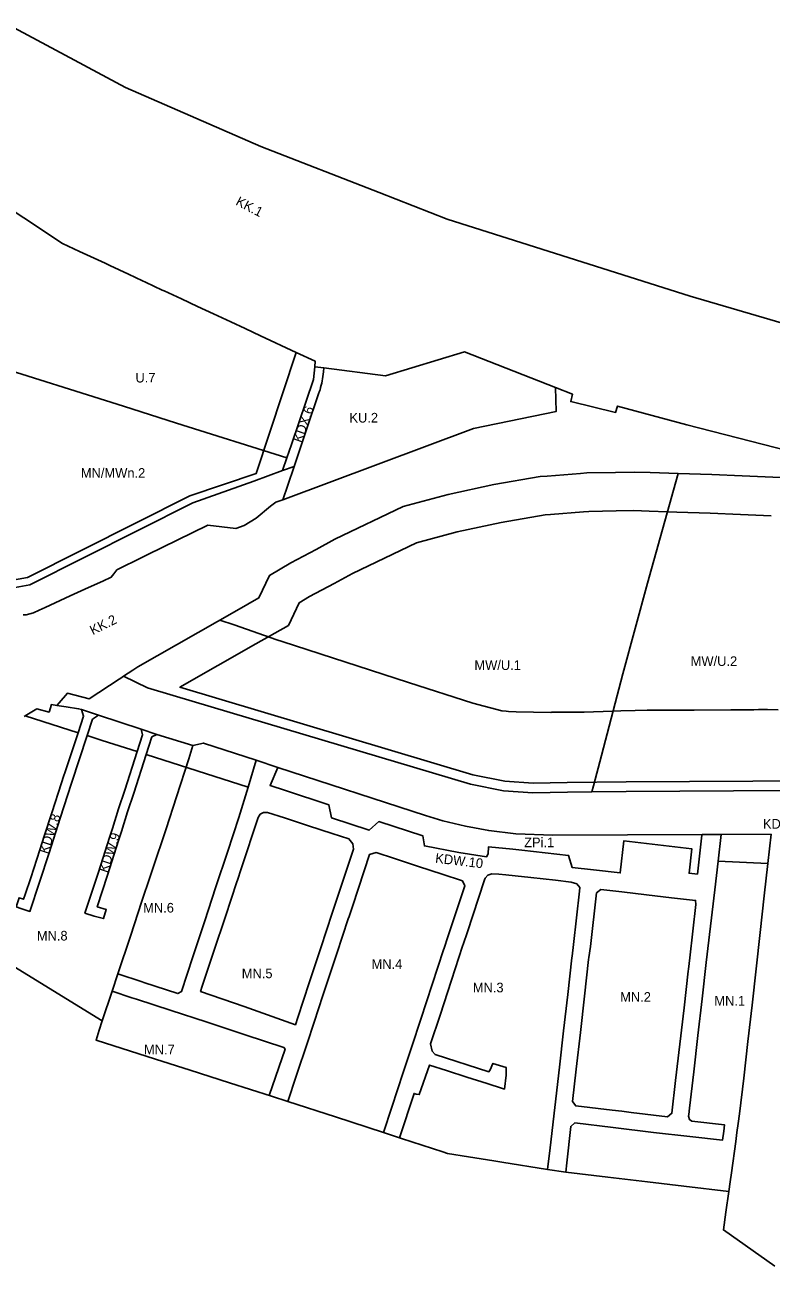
# Model space of a CAD drawing. Extents: x 7416797 to 7419013, y 5549660 to 5551534.
# Drawn here: x 7418242 to 7418629, y 5549800 to 5550444 of the extents above; entities that cross this region are included whole.
import ezdxf

# ---------------------------------------------------------------- set-up
doc = ezdxf.new("R2010")
doc.units = 0
for name, color, linetype in [('LIN_Linia Zabudowy Nieprzekraczalna', 7, 'Continuous'), ('LIN_linie_rozgraniczajace', 7, 'Continuous'), ('LIN_nieprzekraczalna_linia_regulacyjna', 7, 'Continuous'), ('TXT_Oznaczenia_przeznaczen', 7, 'Continuous')]:
    doc.layers.add(name, color=color, linetype=linetype)

msp = doc.modelspace()

# ---------------------------------------------------------------- linework, layer by layer
at = {"layer": 'LIN_Linia Zabudowy Nieprzekraczalna'}
for p, q in [((7418269.2, 5550076.38), (7418241.83, 5550085.15)), ((7418357.44, 5550048.11), (7418304.63, 5550065.03)), ((7418627.34, 5550008.51), (7418601.44, 5550009.72))]:
    msp.add_line(p, q, dxfattribs=at)
for points in [[(7418176.38, 5550170.79), (7418226.4, 5550154.02), (7418242.97, 5550156.96), (7418327.21, 5550199.31), (7418361.69, 5550210.89), (7418382.5, 5550273.76)], [(7418629.07, 5550188.98), (7418613.18, 5550189.67), (7418597.42, 5550190.36), (7418580.12, 5550190.91), (7418575.19, 5550191.07), (7418565.63, 5550191.37), (7418557.7, 5550191.62), (7418548.59, 5550191.48), (7418534.35, 5550191.24), (7418531.68, 5550191.03), (7418514.41, 5550189.66), (7418511.65, 5550189.44), (7418488.94, 5550185.54), (7418466.05, 5550180.56), (7418444.95, 5550174.87), (7418411.67, 5550158.98), (7418402.25, 5550153.85), (7418389.45, 5550147.01), (7418384.01, 5550143.85), (7418378.54, 5550132.09), (7418361.57, 5550122.44), (7418322.07, 5550099.95), (7418474.11, 5550054.46), (7418490.77, 5550051.25), (7418505.48, 5550050.15), (7418523.15, 5550050.5), (7418553.78, 5550050.88), (7418882.6, 5550052.65)], [(7418299.87, 5550066.55), (7418281.75, 5550072.42), (7418273.95, 5550074.87)]]:
    msp.add_lwpolyline(points, dxfattribs=at)
at = {"layer": 'LIN_linie_rozgraniczajace'}
for p, q in [((7418396.67, 5550263.6), (7418396.84, 5550265.7)), ((7418593.15, 5550023.56), (7418603.02, 5550023.61))]:
    msp.add_line(p, q, dxfattribs=at)
for points in [[(7418216.45, 5550452.52), (7418293.85, 5550411.16), (7418364.15, 5550380.58), (7418425.56, 5550356.68), (7418460.75, 5550342.97), (7418587.07, 5550302.96), (7418652.56, 5550283.78)], [(7418392.15, 5550266.3), (7418392.28, 5550269.21), (7418382.5, 5550273.76), (7418363.87, 5550282.44), (7418355.95, 5550286.12), (7418348.45, 5550289.62), (7418339.49, 5550293.79), (7418331.21, 5550297.64), (7418322.84, 5550301.53), (7418313.92, 5550305.69), (7418312.96, 5550306.14), (7418304.3, 5550310.28), (7418302.75, 5550310.89), (7418295.33, 5550314.34), (7418285.69, 5550318.83), (7418283.2, 5550319.99), (7418270, 5550326.12), (7418261.14, 5550330.25), (7418253.52, 5550335.3), (7418245.06, 5550340.92), (7418232.56, 5550349.21), (7418230.4, 5550351.03)], [(7418209.31, 5550290.14), (7418226.55, 5550285.12), (7418225.73, 5550282.58), (7418221.11, 5550268.3), (7418292.87, 5550245.8), (7418320.28, 5550237.08), (7418377.67, 5550219.01)], [(7418517.12, 5550255.55), (7418469.86, 5550274.03), (7418428.76, 5550261.65), (7418396.84, 5550265.7)], [(7418392.15, 5550266.3), (7418391.42, 5550259.74), (7418380.04, 5550226.04), (7418377.67, 5550219.01)], [(7418396.84, 5550265.7), (7418392.15, 5550266.3)], [(7418375.58, 5550197.32), (7418474.5, 5550234.31), (7418517.4, 5550243.02), (7418517.12, 5550255.55)], [(7418517.12, 5550255.55), (7418525.82, 5550252.15), (7418525.02, 5550248.2), (7418548.28, 5550242.6), (7418549.21, 5550245.86), (7418585.2, 5550236.1), (7418677.71, 5550212.39), (7418677.52, 5550210.42), (7418677.18, 5550206.89)], [(7418381.38, 5550214.53), (7418387.84, 5550233.7), (7418394.29, 5550252.7)], [(7418377.67, 5550219.01), (7418375.43, 5550212.39)], [(7418375.43, 5550212.39), (7418360.4, 5550206.99), (7418328.79, 5550195.63), (7418244.25, 5550153.12), (7418226.9, 5550150.05), (7418205.6, 5550155.1), (7418187.63, 5550158.95), (7418186.67, 5550163.27), (7418172.05, 5550168.19)], [(7418292.83, 5550105.67), (7418297.72, 5550108.89), (7418300.17, 5550110.5), (7418351.68, 5550139.82), (7418363.1, 5550146.32), (7418368.53, 5550157.98), (7418379.71, 5550164.48), (7418392.75, 5550171.45), (7418402.57, 5550176.8), (7418437.98, 5550193.7), (7418461.31, 5550200), (7418485.12, 5550205.18), (7418509.14, 5550209.3), (7418512.81, 5550209.6), (7418530.1, 5550210.97), (7418533.39, 5550211.23), (7418548.27, 5550211.48), (7418557.87, 5550211.63), (7418566.27, 5550211.36), (7418580.75, 5550210.9)], [(7418381.38, 5550214.53), (7418375.43, 5550212.39)], [(7418375.58, 5550197.32), (7418378.14, 5550204.92), (7418381.38, 5550214.53)], [(7418580.75, 5550210.9), (7418566.91, 5550161.5), (7418564.83, 5550153.93), (7418551.95, 5550107.01), (7418540.93, 5550064.5), (7418536.87, 5550048.89), (7418536.01, 5550045.66)], [(7418580.75, 5550210.9), (7418598.18, 5550210.35), (7418614.05, 5550209.65), (7418629.94, 5550208.96), (7418662.13, 5550207.55), (7418677.18, 5550206.89)], [(7418375.58, 5550197.32), (7418371.92, 5550195.95), (7418369.19, 5550193.9), (7418361.64, 5550187.73), (7418355.42, 5550183.84), (7418351.11, 5550182.36), (7418336.6, 5550184.09), (7418305.12, 5550168.7), (7418302.67, 5550167.47), (7418289.41, 5550160.86), (7418287.83, 5550158.81), (7418286.47, 5550157.04), (7418282.03, 5550154.99), (7418274.66, 5550151.7), (7418265.05, 5550147.35), (7418252.12, 5550141.36), (7418248.97, 5550139.9), (7418246.11, 5550138.58), (7418242.31, 5550137.6), (7418240.7, 5550137.5)], [(7418258.27, 5550090.51), (7418259.45, 5550091.89), (7418263.7, 5550096.86), (7418275.01, 5550093.97), (7418290.54, 5550104.16), (7418291.36, 5550104.7), (7418292.83, 5550105.67)], [(7418292.83, 5550105.67), (7418305.3, 5550099.75), (7418318.61, 5550095.77), (7418472.92, 5550049.6), (7418490.11, 5550046.29), (7418505.34, 5550045.15), (7418523.25, 5550045.5), (7418536.01, 5550045.66)], [(7418279.79, 5550085.49), (7418276.77, 5550083.41), (7418273.95, 5550074.86), (7418265.8, 5550050.2), (7418259.95, 5550032.09), (7418254.13, 5550014.04), (7418244.19, 5549983.62), (7418239.43, 5549985.16), (7418237.02, 5549985.94), (7418238.57, 5549990.7), (7418240.94, 5549989.93), (7418241.74, 5549992.44), (7418244.73, 5550001.12), (7418249.36, 5550015.57), (7418251.63, 5550022.67), (7418255.52, 5550034.79), (7418260.59, 5550050.4), (7418261.66, 5550053.58), (7418262.49, 5550056.06), (7418269.2, 5550076.38), (7418272.04, 5550085), (7418270.92, 5550088.36)], [(7418258.27, 5550090.51), (7418255.37, 5550090.95), (7418254.21, 5550087.12), (7418247.85, 5550088.77), (7418241.83, 5550085.15), (7418241.32, 5550084.85)], [(7418258.27, 5550090.51), (7418263.01, 5550089.79), (7418269.47, 5550088.8), (7418270.92, 5550088.36)], [(7418270.92, 5550088.36), (7418279.79, 5550085.49)], [(7418279.79, 5550085.49), (7418302.02, 5550078.14)], [(7418302.02, 5550078.14), (7418302.68, 5550075.28), (7418299.87, 5550066.55), (7418293.43, 5550046.52), (7418290.18, 5550036.89), (7418287.02, 5550026.75), (7418285.51, 5550021.92), (7418279.79, 5550004.04), (7418273.16, 5549983.83), (7418272.81, 5549982.78), (7418277.56, 5549981.21), (7418282.38, 5549979.88), (7418283.84, 5549984.66), (7418279.16, 5549986.08), (7418284.55, 5550002.5), (7418290.28, 5550020.41), (7418291.75, 5550025.11), (7418294.94, 5550035.35), (7418298.18, 5550044.96), (7418304.63, 5550065.03), (7418306.02, 5550069.35), (7418307.58, 5550074.19), (7418310.17, 5550075.47)], [(7418302.02, 5550078.14), (7418310.17, 5550075.47)], [(7418310.17, 5550075.47), (7418328.87, 5550069.71)], [(7418328.87, 5550069.71), (7418326.66, 5550062.91), (7418320.26, 5550043.11), (7418314.9, 5550026.58), (7418314.38, 5550025.01), (7418308.36, 5550006.96), (7418306.63, 5550001.78), (7418302.38, 5549988.91), (7418296.38, 5549970.81), (7418289.91, 5549951.25)], [(7418328.87, 5550069.71), (7418334.29, 5550070.99), (7418361.7, 5550062.06)], [(7418289.91, 5549951.25), (7418302.45, 5549947.13), (7418303.41, 5549946.82), (7418321.03, 5549941.03), (7418322.92, 5549942.05), (7418328.85, 5549960.14), (7418334.83, 5549978.23), (7418340.76, 5549996.31), (7418346.72, 5550014.38), (7418352.67, 5550032.46), (7418357.44, 5550048.11), (7418361.7, 5550062.06)], [(7418361.7, 5550062.06), (7418372.95, 5550058.4)], [(7418593.15, 5550023.56), (7418593.09, 5550023.15), (7418590.78, 5550003), (7418586.43, 5550003.41), (7418587.88, 5550016.03), (7418552.53, 5550020.25), (7418550.71, 5550003.59), (7418536.77, 5550005.18), (7418525.68, 5550006.49), (7418523.87, 5550012.74), (7418499.61, 5550015.35), (7418494.9, 5550016.02), (7418482.25, 5550017.1), (7418482.06, 5550013.46), (7418481.28, 5550012), (7418466.91, 5550014.26), (7418449.06, 5550017.63), (7418448.24, 5550022.82), (7418425.43, 5550030.29), (7418420.32, 5550025.78), (7418400.83, 5550032.14), (7418399.47, 5550038.95), (7418376.86, 5550046.47), (7418368.93, 5550049.01), (7418372.95, 5550058.4)], [(7418372.95, 5550058.4), (7418449.5, 5550033.47), (7418458.67, 5550030.72), (7418470.4, 5550027.84), (7418482.38, 5550025.62), (7418496.5, 5550023.92), (7418515.63, 5550023.15), (7418593.15, 5550023.56)], [(7418536.01, 5550045.66), (7418553.84, 5550045.88), (7418637.27, 5550046.33)], [(7418603.02, 5550023.61), (7418601.44, 5550009.72), (7418599.73, 5549994.75), (7418597.5, 5549975.9), (7418595.34, 5549957.06), (7418593.17, 5549938.19), (7418591, 5549919.3), (7418588.83, 5549900.39), (7418586.64, 5549881.5), (7418586.25, 5549878.25), (7418586.1, 5549877.44), (7418586.64, 5549875.6), (7418587.87, 5549874.81), (7418604.75, 5549872.88), (7418604.38, 5549869.61), (7418603.85, 5549864.95), (7418586.75, 5549866.86), (7418568.03, 5549868.94), (7418547.06, 5549871.53), (7418527.19, 5549873.85), (7418524.97, 5549872.09), (7418522.93, 5549853.23), (7418522.4, 5549848.25)], [(7418603.02, 5550023.61), (7418629.04, 5550023.75)], [(7418607.07, 5549838.29), (7418607.78, 5549843.25), (7418608.45, 5549847.99), (7418610.65, 5549864.21), (7418611.27, 5549868.86), (7418611.9, 5549873.51), (7418612.58, 5549878.55), (7418614.85, 5549897.13), (7418616.98, 5549916.18), (7418619.1, 5549935.06), (7418621.21, 5549953.91), (7418623.32, 5549972.72), (7418625.46, 5549991.77), (7418627.34, 5550008.51), (7418629.04, 5550023.75)], [(7418427.75, 5549868.85), (7418432.1, 5549882.01), (7418438.06, 5549900.06), (7418444.02, 5549918.16), (7418445.65, 5549923.1), (7418447.14, 5549927.66), (7418453.09, 5549945.72), (7418459.01, 5549963.78), (7418459.27, 5549964.57), (7418461.19, 5549970.44), (7418469.95, 5549996.9), (7418468.71, 5549999.47), (7418458.23, 5550002.92), (7418445.9, 5550006.99), (7418433.53, 5550011.06), (7418424.04, 5550014.18), (7418420.56, 5550013.23), (7418411.8, 5549986.62), (7418409.9, 5549981.04), (7418409.51, 5549979.86), (7418403.55, 5549961.8), (7418397.58, 5549943.71), (7418396, 5549938.93), (7418394.45, 5549934.2), (7418388.44, 5549916.14), (7418382.47, 5549898.09), (7418378.19, 5549885.02)], [(7418512.94, 5549849.68), (7418514.28, 5549860.96), (7418516.69, 5549881.81), (7418519.09, 5549902.8), (7418521.27, 5549921.68), (7418523.44, 5549940.58), (7418525.58, 5549959.47), (7418525.69, 5549960.47), (7418526.35, 5549966.45), (7418529.6, 5549994.08), (7418529.74, 5549996.09), (7418528.12, 5549998.02), (7418525.24, 5549998.9), (7418517.15, 5549999.81), (7418504.21, 5550001.28), (7418496.21, 5550002.18), (7418491.29, 5550002.63), (7418487.74, 5550002.95), (7418484.07, 5550003.21), (7418481.96, 5550002.46), (7418480.57, 5550000.97), (7418480.15, 5549999.99), (7418471.18, 5549972.56), (7418469.28, 5549967.02), (7418468.81, 5549965.67), (7418463.01, 5549947.94), (7418457.12, 5549929.85), (7418452.23, 5549914.94), (7418453.11, 5549911.19), (7418454.65, 5549909.37), (7418482.53, 5549900.43), (7418483.15, 5549901.39), (7418484.6, 5549904.78), (7418491.51, 5549902.55), (7418491.5, 5549898.66), (7418490.58, 5549891.41), (7418489.63, 5549891.71), (7418481.53, 5549894.3), (7418470.97, 5549897.69), (7418460.43, 5549901.07), (7418451.74, 5549903.85), (7418446.32, 5549888.56), (7418444.73, 5549888.86), (7418443.69, 5549889.2), (7418436.06, 5549866.14)], [(7418631, 5549799.52), (7418604.21, 5549818.33), (7418605.52, 5549827.5), (7418607.07, 5549838.29), (7418583.78, 5549841.03), (7418564.91, 5549843.25), (7418544.2, 5549845.68), (7418522.4, 5549848.25), (7418512.94, 5549849.68), (7418489.21, 5549853.55), (7418486.05, 5549854.07), (7418485.06, 5549854.23), (7418471.93, 5549856.31), (7418460.95, 5549858.05), (7418458.51, 5549858.84), (7418447.88, 5549862.3), (7418437.18, 5549865.77), (7418436.06, 5549866.14), (7418427.75, 5549868.85), (7418402.93, 5549876.94), (7418378.19, 5549885.02), (7418369.69, 5549887.73), (7418347.77, 5549894.73), (7418327.48, 5549901.21), (7418309.37, 5549906.99), (7418278.58, 5549916.83), (7418280.24, 5549922.03), (7418281.81, 5549926.8), (7418281.81, 5549926.8), (7418222.22, 5549963.42)], [(7418289.91, 5549951.25), (7418289.07, 5549948.72), (7418287.8, 5549944.89), (7418286.91, 5549942.22)], [(7418286.91, 5549942.22), (7418281.81, 5549926.8)], [(7418368.46, 5549888.12), (7418376.7, 5549912.23), (7418376.08, 5549913.02), (7418355.97, 5549919.56), (7418335.7, 5549926.27), (7418317.59, 5549932.19), (7418299.48, 5549938.11), (7418297.18, 5549938.86), (7418286.91, 5549942.22)]]:
    msp.add_lwpolyline(points, dxfattribs=at)
for points in [[(7418388.82, 5550028.13), (7418376.44, 5550032.12), (7418367.58, 5550034.98), (7418365.47, 5550035.01), (7418363.71, 5550034.08), (7418362.75, 5550032.32), (7418353.86, 5550005.65), (7418352, 5549999.87), (7418351.72, 5549999.02), (7418345.7, 5549980.95), (7418339.7, 5549962.94), (7418333.72, 5549944.83), (7418332.8, 5549942.08), (7418355.38, 5549934.33), (7418382.02, 5549924.8), (7418383.24, 5549928.54), (7418389.24, 5549946.61), (7418395.23, 5549964.68), (7418401.19, 5549982.73), (7418401.54, 5549983.78), (7418403.42, 5549989.43), (7418412.16, 5550015.95), (7418411.91, 5550018.76), (7418409.86, 5550021.36), (7418401.2, 5550024.15)], [(7418588.21, 5549989.46), (7418577.31, 5549990.73), (7418564.4, 5549992.25), (7418551.5, 5549993.74), (7418540.59, 5549995.03), (7418538.39, 5549993.27), (7418535.18, 5549965.48), (7418534.41, 5549959.65), (7418534.27, 5549958.6), (7418532.14, 5549939.7), (7418529.97, 5549920.81), (7418527.8, 5549901.85), (7418525.89, 5549884.94), (7418527.61, 5549882.73), (7418546.51, 5549880.51), (7418551.58, 5549879.91), (7418556.42, 5549879.35), (7418575.23, 5549877.09), (7418577.47, 5549878.91), (7418579.43, 5549895.82), (7418581.61, 5549914.8), (7418583.79, 5549933.68), (7418585.98, 5549952.57), (7418586.09, 5549953.6), (7418586.77, 5549959.53), (7418589.99, 5549987.25), (7418589.78, 5549989.34)]]:
    msp.add_lwpolyline(points, close=True, dxfattribs=at)
for start, end in [(343.32374, 354.08076), (341.26935, 343.32374)]:
    msp.add_arc((7418346.93, 5550268.76), 50, start, end, dxfattribs=at)
at = {"layer": 'LIN_nieprzekraczalna_linia_regulacyjna'}
msp.add_lwpolyline([(7418632.63, 5550088.3), (7418627.15, 5550088.37), (7418622.52, 5550088.35), (7418619.99, 5550088.32), (7418608.12, 5550088.28), (7418589, 5550088.15), (7418571.46, 5550088.03), (7418564.62, 5550088), (7418558.5, 5550087.94), (7418551, 5550087.79), (7418546.73, 5550087.64), (7418531.97, 5550087.08), (7418515.23, 5550086.99), (7418514.68, 5550086.95), (7418496.7, 5550087.18), (7418492.59, 5550087.38), (7418491.53, 5550087.48), (7418489.28, 5550087.73), (7418474.18, 5550091.69), (7418440.8, 5550102.4), (7418375.14, 5550123.73), (7418372.47, 5550124.61), (7418350.31, 5550132.3), (7418342.84, 5550134.79)], dxfattribs=at)

# ---------------------------------------------------------------- texts
at = {"layer": 'TXT_Oznaczenia_przeznaczen'}
for s, rotation, p in [('KK.1', 332.72251, (7418350.65, 5550350.51)), ('KDX.6', 70.27741, (7418385.27, 5550226.53)), ('KK.2', 26.75534, (7418276.88, 5550126.92)), ('KDW.8', 71.49622, (7418253.52, 5550013.13)), ('KDW.9', 71.4055, (7418284.46, 5550003.35)), ('KDW.10', 353.18358, (7418454.44, 5550008.94))]:
    msp.add_text(s, height=5, rotation=rotation, dxfattribs=at).set_placement(p)
for s, p in [('U.7', (7418299.01, 5550258.15)), ('KU.2', (7418410.1, 5550237.36)), ('MN/MWn.2', (7418270.66, 5550208.69)), ('MW/U.1', (7418474.98, 5550108.96)), ('MW/U.2', (7418587.26, 5550111.04)), ('KDZ.1', (7418624.77, 5550026.59)), ('ZPi.1', (7418500.78, 5550016.96)), ('MN.6', (7418302.99, 5549983.05)), ('MN.8', (7418247.81, 5549968.53)), ('MN.4', (7418421.59, 5549953.82)), ('MN.5', (7418354.2, 5549948.96)), ('MN.3', (7418474.14, 5549941.63)), ('MN.2', (7418550.65, 5549936.74)), ('MN.1', (7418599.54, 5549934.75)), ('MN.7', (7418303.43, 5549909.44))]:
    msp.add_text(s, height=5, dxfattribs=at).set_placement(p)

doc.saveas('drawing.dxf')
